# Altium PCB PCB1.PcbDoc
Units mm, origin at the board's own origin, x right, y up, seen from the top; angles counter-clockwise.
Board outline 113.54 x 63.88 mm, 2 copper layers (Top Layer, Bottom Layer); 30 components, 31 nets, 121 pads, 42 vias.
Unrouted connection lines stored in the file: 1.
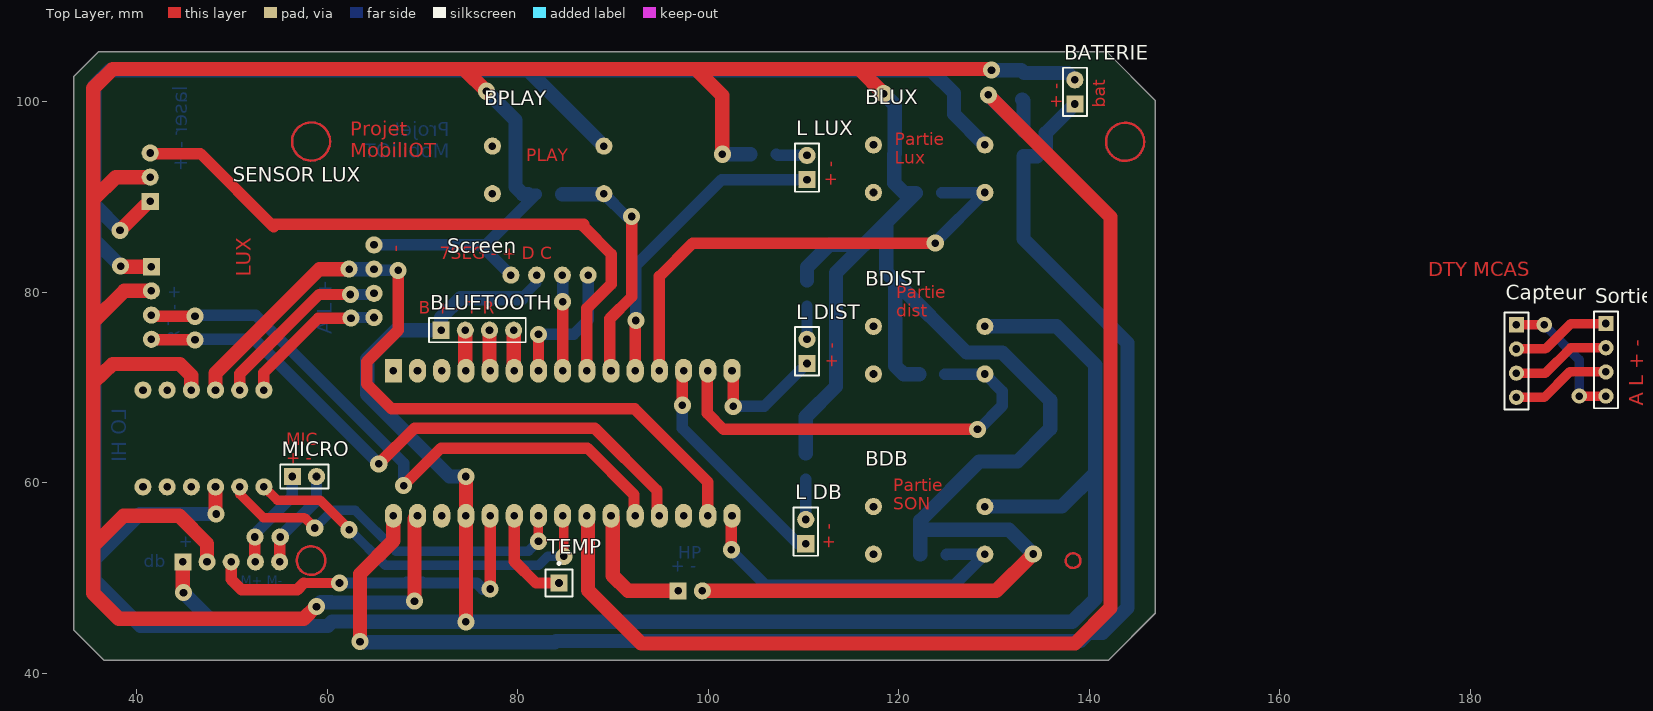
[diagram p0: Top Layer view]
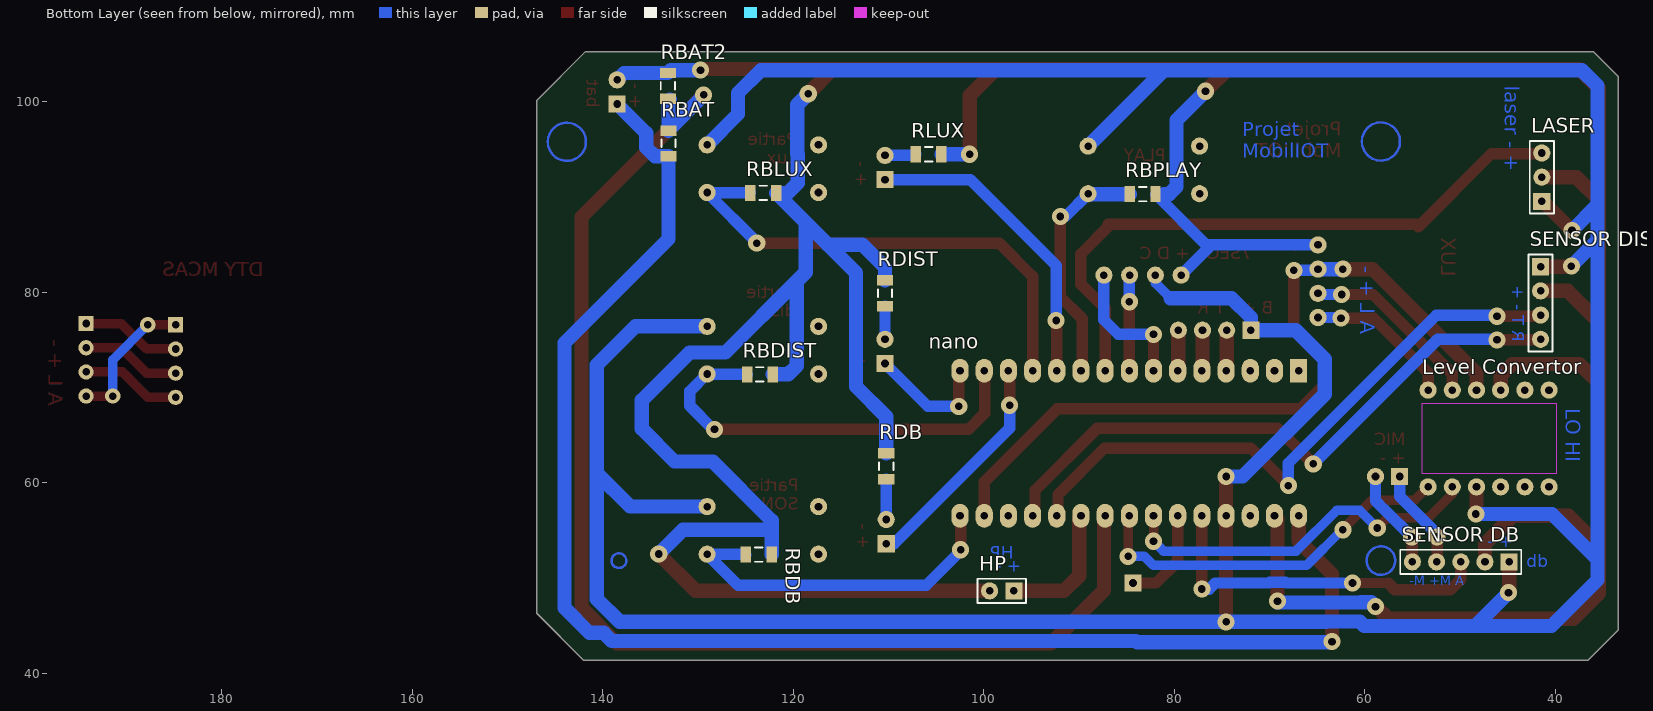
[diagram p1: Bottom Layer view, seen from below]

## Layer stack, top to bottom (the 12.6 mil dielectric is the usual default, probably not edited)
Top Solder: solder mask 0.0102, Solder Resist, Dk 3.5
Top Layer: signal copper 0.0356
Dielectric 1: dielectric 0.32, FR-4, Dk 4.8
Bottom Layer: signal copper 0.0356
Bottom Solder: solder mask 0.0102, Solder Resist, Dk 3.5

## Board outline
33.401,44.514 33.401,102.679 35.941,105.219 141.859,105.219 146.939,100.139 146.939,46.291 141.986,41.338 36.576,41.338

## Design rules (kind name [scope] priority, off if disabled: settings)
Clearance [All] p1: gap=0.254 ignorepadtopadclearanceinfootprint=FALSE except(0: Arc-Hole Track-Hole SMDPad-Hole THPad-Hole Via-Hole Fill-Hole Poly-Hole Region-Hole Text-Hole; 0.5: Arc-Arc Arc-Track Arc-SMDPad Arc-THPad Arc-Via Arc-Fill Arc-Poly Arc-Region Arc-Text Track-Track Track-SMDPad Track-THPad Track-Via Track-Fill Track-Poly Track-Region Track-Text)
PolygonConnect [All] p1: connectstyle=Relief reliefconductorwidth=0.254 reliefentries=4 polygonreliefangle="90 Angle" airgapwidth=0.254
RoutingVias [All] p1: holewidth=0.8 width=1.6 viastyle="Through Hole" minholewidth=0.8 minwidth=1.6 maxholewidth=0.8 maxwidth=1.6
SolderMaskExpansion [All] p1: expansion=0.102
Width [All] p1: maxlimit=1.5 minlimit=1 preferedwidth=1.2
30 further rules are at their usual default settings.

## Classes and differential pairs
component class Sheet1: BATERIE BDB BDIST BLUETOOTH BLUX BPLAY HP "L DB" "L DIST" "L LUX" LASER "Level Convertor" MICRO nano RBAT RBAT2 RBDB RBDIST RBLUX RBPLAY RDB RDIST RLUX Screen "SENSOR DB" "SENSOR DIST" "SENSOR LUX" TEMP

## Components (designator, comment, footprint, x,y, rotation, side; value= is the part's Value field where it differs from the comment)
BATERIE "Header 2" HDR1X2 138.493,99.758 r90 top
BDB "push_button_12_12" push_button_12_12 123.19,54.991 r0 top
BDIST "push_button_12_12" push_button_12_12 123.19,73.914 r0 top
BLUETOOTH "Header 4" HDR1X4#1 71.945,76.01 r0 top
BLUX "push_button_12_12" push_button_12_12 123.19,92.964 r0 top
BPLAY "push_button_12_12" push_button_12_12 83.185,92.837 r0 top
Capteur "Header 4" HDR1X4#2 184.849,76.581 r270 top
HP "Header 2" HDR1X2 96.837,48.641 r0 bottom
"L DB" "Header 2" HDR1X2 110.236,53.594 r90 top
"L DIST" "Header 2" HDR1X2 110.363,72.517 r90 top
"L LUX" "Header 2" HDR1X2 110.363,91.821 r90 top
LASER "Header 3" HDR1X3 41.402,89.535 r90 bottom
"Level Convertor" "3v3 5v" level_convertor 46.863,64.897 r0 bottom
MICRO "Header 2" HDR1X2 56.325,60.642 r0 top
nano "arduinoNano" "Arduino nano" 62.865,73.279 r0 bottom
RBAT "Res3" C1206 133.096,95.615 r270 bottom
RBAT2 "Res3" C1206 133.16,101.663 r270 bottom
RBDB "RB" C1206 123.618,52.451 r0 bottom
RBDIST "RB" C1206 123.491,71.374 r0 bottom
RBLUX "RB" C1206 123.143,90.424 r0 bottom
RBPLAY "RB" C1206 83.312,90.297 r0 bottom
RDB "RDB" C1206 110.236,61.722 r270 bottom
RDIST "R DIST" C1206 110.363,79.883 r270 bottom
RLUX "R LUX" C1206 105.791,94.488 r0 bottom
Screen "4_7_segments" 4_7_segment 87.376,81.788 r90 top
"SENSOR DB" "Header 5" HDR1X5 44.831,51.689 r0 bottom
"SENSOR DIST" "Header 4" HDR1X4#1 41.529,82.677 r270 bottom
"SENSOR LUX" "support_luxmeter" support_luxmeter 54.024,79.971 r0 top
Sorties "Header 4" HDR1X4#2 194.246,76.708 r270 top
TEMP "Plug" PIN1 84.328,49.466 r0 top

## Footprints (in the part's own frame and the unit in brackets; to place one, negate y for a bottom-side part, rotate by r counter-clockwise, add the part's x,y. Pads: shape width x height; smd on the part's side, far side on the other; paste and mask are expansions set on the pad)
4_7_segment [mm]
  round 1.8 hole 0.8: 1(0,0) 2(0,2.7) 3(0,5.4) 4(0,8.1)
  body extent -38.48,-7.94 1.52,15.06, height 12
"Arduino nano" [mm] "arduino nano"
  rect 1.8x2.5 hole 0.8: 0(4.064,1.524)
  oval 1.8x2.5 hole 0.8: 1(6.604,1.524) 2(9.144,1.524) 3(11.684,1.524) 4(14.224,1.524) 5(16.764,1.524) 6(19.304,1.524) 7(21.844,1.524) 8(24.384,1.524) 9(26.924,1.524) 10(29.464,1.524) 11(32.004,1.524) 12(34.544,1.524) 13(37.084,1.524) 14(39.624,1.524) 15(39.624,16.764) 16(37.084,16.764) 17(34.544,16.764) 18(32.004,16.764) 19(29.464,16.764) 20(26.924,16.764) 21(24.384,16.764) 22(21.844,16.764) 23(19.304,16.764) 24(16.764,16.764) 25(14.224,16.764) 26(11.684,16.764) 27(9.144,16.764) 28(6.604,16.764) 29(4.064,16.764)
C1206 [mm] "Chip Capacitor, Body 3.2x1.6mm, IPC High Density"
  rect 1.1x1.7 smd: 1(-1.35,0) 2(1.35,0)
  silkscreen extent -0.4,-0.75 0.4,0.75, body extent -1.7,-0.9 1.7,0.9, height 1.3
HDR1X2 [mm] "Connector; Header; 2 Position"
  rect 1.8x1.8 hole 0.8: 1(0,0)
  round 1.8 hole 0.8: 2(2.54,0)
  silkscreen extent -1.27,-1.27 3.81,1.27
HDR1X3 [mm] "Connector; Header; 3 Position"
  rect 1.8x1.8 hole 0.8: 1(0,0)
  round 1.8 hole 0.8: 2(2.54,0) 3(5.08,0)
  silkscreen extent -1.27,-1.27 6.35,1.27
HDR1X4#1 [mm] "Connector; Header; 4 Position"
  rect 1.8x1.8 hole 0.8: 1(0,0)
  round 1.8 hole 0.8: 2(2.54,0) 3(5.08,0) 4(7.62,0)
  silkscreen extent -1.27,-1.27 8.89,1.27
HDR1X4#2 [mm] "Connector; Header; 4 Position"
  rect 1.6x1.6 hole 0.8: 1(0,0)
  round 1.6 hole 0.8: 2(2.54,0) 3(5.08,0) 4(7.62,0)
  silkscreen extent -1.27,-1.27 8.89,1.27
HDR1X5 [mm] "Connector; Header; 5 Position"
  rect 1.8x1.8 hole 0.8: 1(0,0)
  round 1.8 hole 0.8: 2(2.54,0) 3(5.08,0) 4(7.62,0) 5(10.16,0)
  silkscreen extent -1.27,-1.27 11.43,1.27
level_convertor [mm]
  round 1.8 hole 0.8: 1(6.477,5.334) 2(3.937,5.334) 3(1.397,5.334) 4(-1.143,5.334) 5(-3.683,5.334) 6(-6.223,5.334) 7(6.477,-4.826) 8(3.937,-4.826) 9(1.397,-4.826) 10(-1.143,-4.826) 11(-3.683,-4.826) 12(-6.223,-4.826)
  Top Layer keep-out region: -6.985,3.937 7.112,3.937 7.112,-3.429 -6.985,-3.429
PIN1 [mm] "Connector; Plug"
  rect 1.8x1.8 hole 0.8: 1(0,0)
  silkscreen extent -1.4,-1.4 1.4,2.17
push_button_12_12 [mm]
  round 1.8 hole 0.8: 1(-5.85,-2.5) 2(-5.85,2.5) 3(5.85,2.5) 4(5.85,-2.5)
  body extent -6,-6 6,6, height 12
support_luxmeter [mm]
  round 1.8 hole 0.8: 1(10.873,4.992) 2(10.873,2.452) 3(10.873,-0.088) 4(10.873,-2.628)
  body extent -4.24,-8.11 6.76,10.89, height 0

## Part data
BATERIE HP "L DB" "L DIST" "L LUX" MICRO: "Header, 2-Pin"
BLUETOOTH Capteur "SENSOR DIST" Sorties: "Header, 4-Pin"
LASER: "Header, 3-Pin"
"Level Convertor": library part Level_convertor
RBAT RBAT2: "Resistor"
RBDB RBDIST RBLUX RBPLAY RDB RDIST RLUX: library part Res3, "Resistor"
"SENSOR DB": "Header, 5-Pin"

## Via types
v1: diameter 1.8, hole 0.8, Top Layer to Bottom Layer, 40 vias
v2: diameter 1.6, hole 0.8, Top Layer to Bottom Layer, 2 vias

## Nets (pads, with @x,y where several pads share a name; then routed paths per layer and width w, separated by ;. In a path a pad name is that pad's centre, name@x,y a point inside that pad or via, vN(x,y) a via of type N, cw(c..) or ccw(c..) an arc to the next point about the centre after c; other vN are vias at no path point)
3.3V: "Level Convertor.9" "SENSOR LUX.2" nano.16 | length 82.5
  Top Layer w1.2: v1(67.437,82.296) 67.437,76.01 64.135,72.707 64.135,70.358 66.739,67.754 92.266,67.754 99.949,60.071 nano.16
  Top Layer w1.5: 48.26,69.723 48.26,71.501 59.182,82.423 v1(62.293,82.423)
  Bottom Layer w1.2: 64.897,82.423 65.024,82.296 v1(67.437,82.296)
  Bottom Layer w1.5: v1(62.293,82.423) 64.897,82.423
"B DB": BDB.4 nano.15 RBDB.2 | length 37.3
  Top Layer w1.2: v1(102.425,52.959) 102.425,56.451 nano.15
  Bottom Layer w1.2: v1(102.425,52.959) 102.425,52.832 106.045,49.212 125.762,49.212 BDB.4 125.008,52.491 RBDB.2
"B DIST": BDIST.4 nano.13 RBDIST.2 | length 45.5
  Top Layer w1.2: nano.13 99.885,71.691 99.885,67.31 101.6,65.596 v1(128.27,65.596)
  Bottom Layer w1.2: RBDIST.2 129,71.374 BDIST.4 130.874,69.581 130.874,68.072 128.397,65.596 v1(128.27,65.596)
"B LUX": BLUX.4 nano.11 RBLUX.2 | length 52.3
  Top Layer w1.2: nano.11 94.869,81.661 98.361,85.153 v1(123.825,85.153)
  Bottom Layer w1.2: v1(123.825,85.153) 123.825,85.249 BLUX.4@129,90.424 ; RBLUX.2 BLUX.4@129,90.424 ; BLUX.4 BLUX.4@129,90.424
"B PLAY": BPLAY.4 nano.9 RBPLAY.2 | length 25.5
  Top Layer w1.2: nano.9 89.662,71.882 89.662,77.216 91.948,79.502 v1(91.948,87.947)
  Bottom Layer w1.2: BPLAY.4 91.425,87.947 v1(91.948,87.947)
  Bottom Layer w1.5: RBPLAY.2 88.995,90.297 BPLAY.4
CLK: nano.6 Screen.1 | length 13.9
  Top Layer w1.2: nano.6 v1@82.169,75.12
  Bottom Layer w1.2: v1(82.169,75.565) 85.852,75.565 87.376,77.089 Screen.1
"DB (A)": "SENSOR DB.3" nano.25 | length 37.8
  Top Layer w1: 57.531,49.466 v1(61.277,49.466)
  Top Layer w1.2: 49.911,51.689 49.911,49.847 50.99,48.768 56.832,48.768 57.531,49.466 ; v1(77.089,48.831) nano.25
  Bottom Layer w1.2: v1(61.277,49.466) 68.228,49.466 68.323,49.562 69.98,49.562 70.075,49.466 75.692,49.466 76.327,48.831 v1(77.089,48.831)
DIO: nano.7 Screen.2 | length 10.2
  Top Layer w1.2: v1(84.709,78.994) nano.7 nano.7@84.836,71.882
  Bottom Layer w1.2: Screen.2 84.709,81.755 v1(84.709,78.994)
"DIST (RX vert)": "SENSOR DIST.4" nano.18 | length 65.6
  Top Layer w1.2: 41.529,75.057 41.593,74.993 v1(46.101,74.993) ; v1(65.405,61.976) 69.151,65.722 88.075,65.722 94.615,59.182 94.615,56.769 nano.18
  Bottom Layer w1.2: v1(46.101,74.993) 46.164,75.057 52.324,75.057 v1(65.405,61.976)
"DIST (TX)": "SENSOR DIST.3" nano.19 | length 65.5
  Top Layer w1.2: 41.529,77.597 41.656,77.47 v1(46.101,77.47) ; v1(68.008,59.69) 71.945,63.627 87.312,63.627 92.202,58.737 92.202,56.642 nano.19
  Bottom Layer w1.2: v1(46.101,77.47) 46.228,77.597 52.471,77.597 68.008,62.06 v1(68.008,59.69)
GND: "Level Convertor.10" "SENSOR DB.2" "SENSOR DIST.2" "SENSOR LUX.1" BATERIE.2 BLUETOOTH.2 HP.2 LASER.2 nano.3 nano.28 RBAT2.1 RBDB.1 RBDIST.1 RBLUX.1 RBPLAY.1 RDB.1 RDIST.1 RLUX.1 Screen.4 | length 474
  Top Layer w1.5: LASER.2 37.782,92.075 35.433,89.725 ; 41.529,80.137 38.672,80.137 35.433,76.898 ; 45.72,69.723 45.72,71.247 44.514,72.453 37.465,72.453 35.433,70.549 ; 47.371,51.689 47.371,53.594 44.45,56.515 38.608,56.515 35.433,53.34 ; v1(58.864,46.99) 58.801,46.99 57.531,45.72 38.1,45.72 35.433,48.387 35.433,53.34 ; v1(69.151,47.561) 69.151,56.197 nano.28 ; BLUETOOTH.2 74.486,71.819 nano.3 ; 74.486,103.314 v1(76.708,101.092) ; HP.2 130.238,48.641 v1(134.112,52.514) ; v1(101.473,94.488) 101.473,100.647 98.679,103.441 ; v1(118.427,100.838) 115.824,103.441 ; v1(129.731,103.314) 129.603,103.441 115.824,103.441 ; 35.433,53.34 35.433,70.549 ; 35.433,70.549 35.433,76.898 ; 35.433,76.898 35.433,89.725 ; 35.433,89.725 35.433,101.409 37.465,103.441 98.679,103.441 ; 98.679,103.441 115.824,103.441
  Bottom Layer w1.2: 64.897,84.963 76.101,84.963 ; Screen.4 76.101,84.963 ; 81.09,90.297 RBPLAY.1 76.628,84.963 76.101,84.963
  Bottom Layer w1.5: v1(58.864,46.99) 59.309,47.434 60.41,47.434 60.428,47.416 69.133,47.416 69.151,47.434 v1(69.151,47.561) ; v1(76.708,101.092) 79.756,98.044 79.756,91.059 80.518,90.297 81.09,90.297 ; v1(101.473,94.488) RLUX.1 ; RDB.1 110.236,66.929 113.411,70.104 113.411,82.042 116.364,84.995 ; RDIST.1 110.363,82.614 112.744,84.995 116.364,84.995 ; v1(118.427,100.838) 119.59,99.676 119.59,94.532 119.526,94.469 119.526,91.459 120.562,90.424 RBLUX.1 118.681,87.313 ; RBDIST.1 120.523,71.374 119.634,72.263 119.634,81.153 ; RBDB.1 122.268,55.054 ; v1(129.731,103.314) 132.858,103.314 RBAT2.1 137.779,103.013 BATERIE.2 ; v1(134.112,52.514) 131.572,55.054 122.268,55.054 ; 116.364,84.995 118.681,87.313 ; 118.681,87.313 118.681,82.106 119.634,81.153 ; 119.634,81.153 127.123,73.664 130.869,73.664 135.89,68.644 135.89,65.659 132.461,62.23 128.46,62.23 122.268,56.038 122.268,55.054
HP: HP.1 nano.20 | length 13.9
  Top Layer w1.5: nano.20 89.98,56.325 89.98,50.228 91.567,48.641 HP.1
"L DB": "L DB.1" nano.12 | length 24.1
  Top Layer w1.2: v1(97.282,68.135) 97.282,71.628 nano.12
  Bottom Layer w1.2: v1(97.282,68.135) 97.282,65.722 109.41,53.594 110.236,53.594
"L DIST": "L DIST.1" nano.14 | length 13.4
  Top Layer w1.2: nano.14 102.616,71.628 v1(102.616,68.008)
  Bottom Layer w1.2: v1(102.616,68.008) 105.855,68.008 110.363,72.517
"L LUX": "L LUX.1" nano.10 | length 32.8
  Top Layer w1.2: nano.10 92.329,76.962 v1(92.392,77.025)
  Bottom Layer w1.2: v1(92.392,77.025) 92.392,82.804 101.409,91.821 110.363,91.821
LASER: LASER.3 nano.8 | length 66.1
  Top Layer w1.2: LASER.3 41.465,94.551 46.672,94.551 54.361,86.863 ; 54.356,87.122 86.931,87.122 ; 86.936,86.863 89.789,84.01 89.789,80.835 87.249,78.295 nano.8
"MICRO +": "SENSOR DB.4" MICRO.1 | length 10.6
  Top Layer w1.2: v1(52.387,54.292) 52.387,51.752 52.451,51.689
  Bottom Layer w1.2: v1(52.387,54.292) 52.387,54.61 56.325,58.547 MICRO.1
"MICRO -": "SENSOR DB.5" MICRO.2 | length 10.6
  Top Layer w1.2: 54.991,51.689 54.991,54.229 v1(55.054,54.292)
  Bottom Layer w1.2: v1(55.054,54.292) 55.054,54.313 57.887,57.145 57.907,57.145 58.864,58.102 MICRO.2
"NetL DB_2": "L DB.2" RDB.2 | length 4.2
  Bottom Layer w1.2: 110.236,56.134 RDB.2
"NetL DIST_2": "L DIST.2" RDIST.2 | length 3.5
  Bottom Layer w1.2: 110.363,75.057 RDIST.2
"NetL LUX_2": "L LUX.2" RLUX.2 | length 3.3
  Bottom Layer w1.2: RLUX.2 107.268,94.361 110.363,94.361
"NIV BAT": nano.21 RBAT2.2 RBAT.1 | length 134.3
  Top Layer w1.5: nano.21 87.376,56.388 87.376,48.704 92.964,43.116 138.493,43.116 142.24,46.863 142.24,87.884 v1(129.413,100.711)
  Bottom Layer w1.5: v1(129.413,100.711) 129.413,100.647 RBAT.1 133.096,100.107 RBAT2.2@132.969,100.234
"RX Bluetooth": BLUETOOTH.4 nano.5 | length 4.3
  Top Layer w1.5: BLUETOOTH.4 79.566,71.819 nano.5
"SCL 3V": "Level Convertor.8" "SENSOR LUX.3" | length 19.3
  Top Layer w1.2: 50.8,69.723 50.8,71.425 59.131,79.756 v1(62.42,79.756)
  Bottom Layer w1.2: v1(62.42,79.756) 64.77,79.756 64.897,79.883
"SCL 5V": "Level Convertor.2" nano.23 | length 39.2
  Top Layer w1: 50.8,59.563 50.8,58.801 53.276,56.325 57.594,56.325 v1(58.674,55.245) ; v1(82.169,53.848) nano.23
  Bottom Layer w1: v1(58.674,55.245) 60.515,57.087 62.928,57.087 67.207,52.808 81.129,52.808 v1(82.169,53.848)
"SDA 3V": "Level Convertor.7" "SENSOR LUX.4" | length 15.8
  Top Layer w1.2: 53.34,69.723 53.34,71.561 59.059,77.279 v1(62.484,77.279)
  Bottom Layer w1.2: v1(62.484,77.279) 62.547,77.343 64.897,77.343
"SDA 5V": "Level Convertor.1" nano.22 | length 39.7
  Top Layer w1: 53.34,59.563 54.737,58.166 59.245,58.166 62.293,55.118 v1(62.293,55.054) ; nano.22 84.836,56.388 v1(84.836,52.261)
  Bottom Layer w1: v1(62.293,55.054) 62.357,55.054 66.103,51.308 82.175,51.308 83.127,52.261 v1(84.836,52.261)
TEMP: nano.24 TEMP.1 | length 10.4
  Top Layer w1.2: nano.24 79.629,51.752 81.915,49.466 TEMP.1
"TX Bluetooth": BLUETOOTH.3 nano.4 | length 4.3
  Top Layer w1.5: BLUETOOTH.3 77.025,71.819 nano.4
VCC: "Level Convertor.3" "SENSOR DB.1" "SENSOR DIST.1" BDB.3 BDIST.3 BLUETOOTH.1 BLUX.3 BPLAY.3 LASER.1 nano.26 Screen.3 | length 418
  Top Layer w1.5: v1(38.227,86.487) 41.275,89.535 LASER.1 ; v1(38.291,82.74) 38.354,82.677 41.529,82.677 ; 44.831,51.689 44.831,48.514 v1(44.895,48.45) ; 48.26,59.563 48.26,56.769 v1(48.323,56.706) ; v1(74.549,45.384) 74.549,56.388 74.486,56.451 nano.26 v1(74.549,60.642)
  Bottom Layer w1: 80.391,79.375 81.976,80.96 Screen.3
  Bottom Layer w1.5: v1(38.227,86.487) 35.623,89.09 35.56,89.09 ; v1(38.291,82.74) 35.56,85.471 ; v1(44.895,48.45) 48.387,44.958 ; v1(48.323,56.706) 40.322,56.706 35.56,51.943 ; 64.008,45.384 138.221,45.384 140.621,47.784 140.621,60.992 ; 64.226,45.417 60.53,45.417 60.053,44.94 48.405,44.94 48.387,44.958 ; v1(74.549,60.642) 72.834,60.642 64.198,69.278 64.198,72.962 67.246,76.01 BLUETOOTH.1 71.945,77.343 73.977,79.375 80.391,79.375 ; BPLAY.3 81.058,103.314 ; BDB.3 137.12,57.491 140.621,60.992 ; BDIST.3 136.565,76.414 140.621,72.358 140.621,60.992 ; BLUX.3 125.793,98.711 125.793,100.901 123.38,103.314 81.058,103.314 ; 35.56,51.943 35.56,85.471 ; 35.56,51.943 35.56,49.784 40.386,44.958 48.387,44.958 ; 35.56,85.471 35.56,89.09 ; 35.56,89.09 35.56,101.663 37.211,103.314 81.058,103.314
Vin: BATERIE.1 nano.29 RBAT.2 | length 157.3
  Top Layer w1.5: v1(63.436,43.307) 63.436,50.419 66.929,53.911 nano.29
  Bottom Layer w1.5: v1(63.436,43.307) 63.436,43.243 73.649,43.243 73.658,43.234 83.875,43.234 84.025,43.385 139.05,43.385 139.893,44.228 141.383,44.228 144.018,46.863 144.018,74.676 133.096,85.598 RBAT.2 134.524,94.265 135.445,95.186 135.445,96.71 BATERIE.1
pads on no net: "Level Convertor.4" "Level Convertor.5" "Level Convertor.6" "Level Convertor.11" "Level Convertor.12" BDB.1 BDB.2 BDIST.1 BDIST.2 BLUX.1 BLUX.2 BPLAY.1 BPLAY.2 Capteur.1 Capteur.2 Capteur.3 Capteur.4 nano.0 nano.1 nano.2 nano.17 nano.27 Sorties.1 Sorties.2 Sorties.3 Sorties.4
copper on no net: | length 46.2
  Top Layer w1: 184.849,68.961 187.769,68.961 190.436,71.628 194.246,71.628 ; 184.849,71.501 187.897,71.501 190.564,74.168 194.246,74.168 ; 184.849,74.041 187.897,74.041 190.564,76.708 194.246,76.708 ; 184.849,76.581 v2(187.769,76.581) ; v2(191.452,69.088) 194.246,69.088
  Bottom Layer w1: v2(187.769,76.581) 191.452,72.898 v2(191.452,69.088)

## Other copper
Top Layer:
  text "bat" at 141.668,99.377 h1.3 r90
  text "+ -" at 137.096,99.251 h1.3 r90
  text "Projet / MobilIOT" at 62.42,94.17 h1.5
  text "PLAY" at 80.899,93.726 h1.3
  text "Partie / Lux" at 119.57,93.472 h1.3
  text "+ -" at 113.411,91.059 h1.3 r90
  text "-" at 67.818,84.201 h1.52 r90
  text "7SEG - + D C" at 71.819,83.439 h1.3
  text "DTY MCAS" at 175.577,81.661 h1.5
  text "LUX" at 51.943,81.597 h1.52 r90
  text "B + - T R" at 69.596,77.724 h1.3
  text "Partie / dist" at 119.761,77.406 h1.3
  text "+ -" at 113.538,72.009 h1.3 r90
  text "A L + -" at 198.183,68.072 h1.5 r90
  text "MIC / + -" at 55.689,61.976 h1.3
  text "Partie / SON" at 119.444,57.15 h1.3
  text "+ -" at 113.221,53.023 h1.3 r90
Bottom Layer:
  text "laser - +" at 45.276,101.663 h1.52 r90
  text "Projet / MobilIOT" at 72.834,94.107 h1.5
  text "A L + -" at 60.452,75.565 h1.52 r90
  text "R T - +" at 44.514,74.803 h1.25 r90
  text "-" at 46.228,72.326 h1.52 r180
  text "LO HI" at 38.862,67.818 h1.52 r90
  text "+ -" at 44.386,53.213 h1.3
  text "HP" at 96.837,52.006 h1.3
  text "db" at 40.703,51.117 h1.3
  text "+ -" at 96.075,50.673 h1.3
  text "A M+ M-" at 49.53,49.212 h1
Multi-Layer:
  circle w0.254: c58.293,51.816 r1.5
  circle w0.254: c58.293,95.822 r2
  circle w0.254: c143.764,95.786 r2
  lines w0.254: 139.068,51.707 cw(c138.303,51.816) 139.073,51.752

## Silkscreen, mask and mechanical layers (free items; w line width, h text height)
Mechanical 1:
  lines w0.254: 33.401,44.514 33.401,102.679 35.941,105.219 141.859,105.219 146.939,100.139 146.939,46.291 141.986,41.338 36.576,41.338 33.401,44.514 ; 173.165,65.151 173.165,82.804 175.07,84.709 197.421,84.709 199.581,82.55 199.581,64.77 198.056,63.246 175.07,63.246 173.165,65.151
